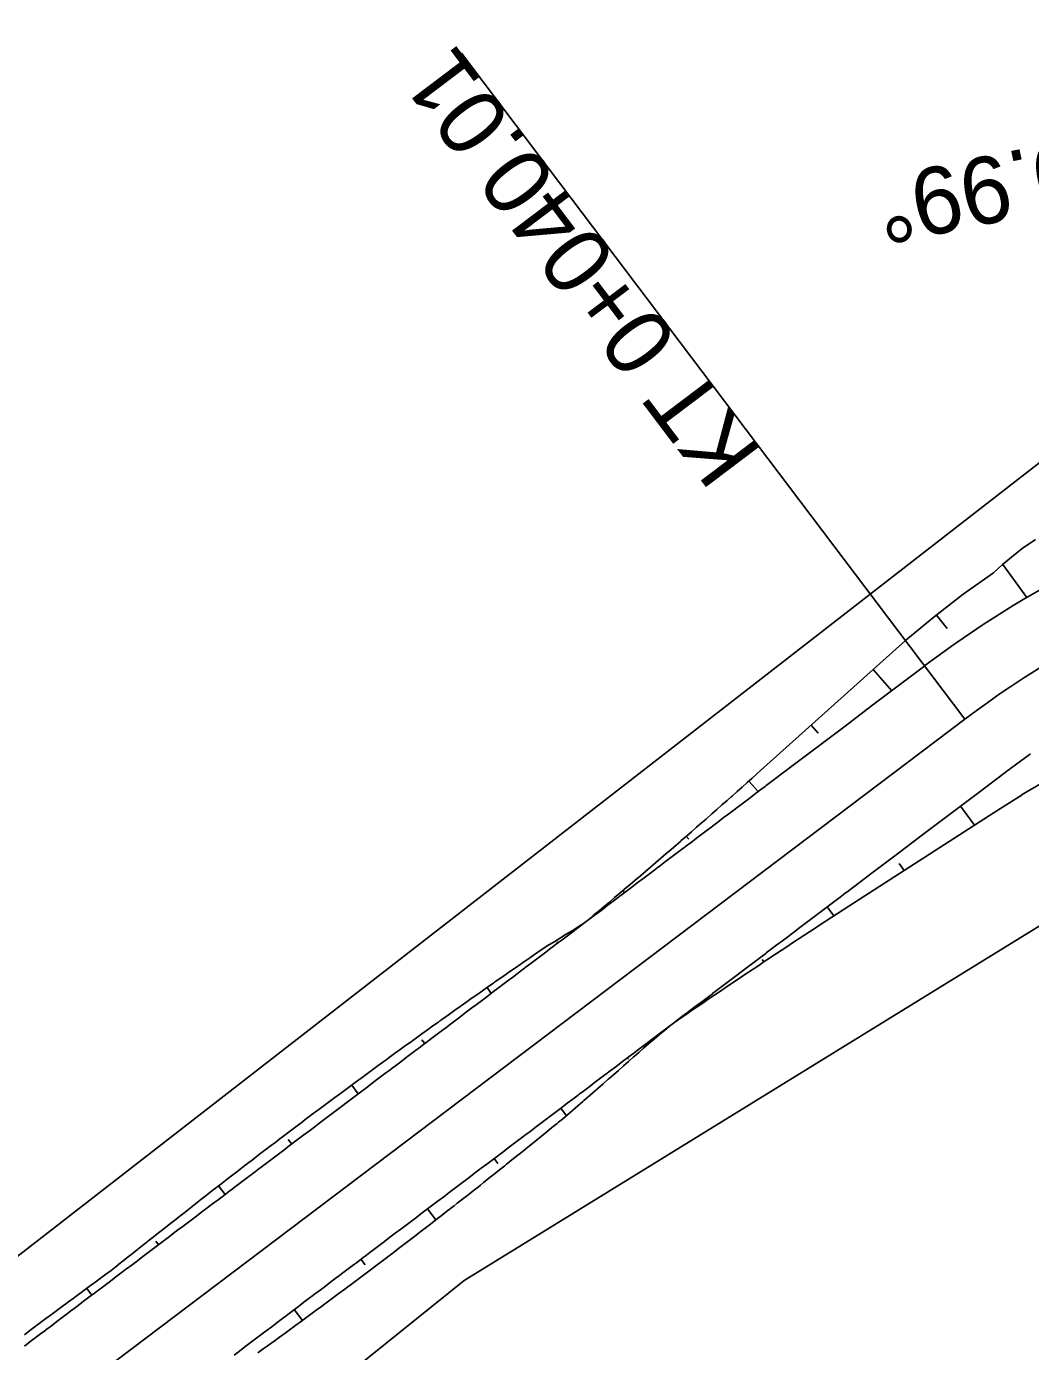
# Model space of a CAD drawing. Extents: x -583470 to -583050, y -1165714 to -1165417.
# Drawn here: x -583260.41 to -583230.35, y -1165547.32 to -1165507.64 of the extents above; entities that cross this region are included whole.
import ezdxf

# ---------------------------------------------------------------- set-up
doc = ezdxf.new("R2010")
doc.units = 0
for name, color, linetype in [('Hranice parcel', 7, 'Continuous'), ('Parcelní čísla', 7, 'Continuous'), ('Rám', 7, 'Continuous'), ('Sítě', 7, 'Continuous'), ('Šrafy', 7, 'Continuous')]:
    doc.layers.add(name, color=color, linetype=linetype)

msp = doc.modelspace()

# ---------------------------------------------------------------- linework, layer by layer
at = {"layer": 'Hranice parcel'}
msp.add_lwpolyline([(-583232.311, -1165528.379), (-583247.383, -1165508.433)], dxfattribs=at)
at = {"layer": 'Parcelní čísla'}
msp.add_line((-583232.311, -1165528.379), (-583286.571, -1165569.38), dxfattribs=at)
msp.add_arc((-583214.224, -1165552.314), 30, 76.0815, 127.0765, dxfattribs=at)
at = {"layer": 'Rám'}
for points in [[(-583348.01, -1165573.19), (-583304.26, -1165570.92), (-583288.23, -1165565.85), (-583222.91, -1165515.13), (-583194.86, -1165515.1)], [(-583202.69, -1165538.68), (-583225.12, -1165531.51), (-583247.31, -1165545.19), (-583283.21, -1165574.06), (-583292.71, -1165580.22), (-583304.73, -1165581.14), (-583316.86, -1165578.96), (-583335.26, -1165581.29), (-583341.42, -1165583.09), (-583347.21, -1165586.62), (-583351.13, -1165592.35), (-583353.34, -1165595.85), (-583354.98, -1165601.64), (-583352.56, -1165623.43)]]:
    msp.add_lwpolyline(points, dxfattribs=at)
at = {"layer": 'Sítě'}
for points in [[(-583260.474, -1165546.812), (-583260.313, -1165546.691), (-583260.151, -1165546.57), (-583259.999, -1165546.456), (-583259.989, -1165546.449), (-583259.828, -1165546.328), (-583259.666, -1165546.208), (-583259.504, -1165546.088), (-583259.342, -1165545.968), (-583259.196, -1165545.86), (-583259.18, -1165545.848), (-583259.017, -1165545.728), (-583258.855, -1165545.608), (-583258.692, -1165545.489), (-583258.53, -1165545.369), (-583258.391, -1165545.267), (-583258.367, -1165545.25), (-583258.204, -1165545.131), (-583258.041, -1165545.012), (-583257.878, -1165544.893), (-583257.721, -1165544.767), (-583257.593, -1165544.664), (-583257.563, -1165544.64), (-583257.406, -1165544.514), (-583257.248, -1165544.388), (-583257.09, -1165544.263), (-583256.932, -1165544.137), (-583256.81, -1165544.041), (-583256.773, -1165544.012), (-583256.615, -1165543.888), (-583256.456, -1165543.764), (-583256.297, -1165543.639), (-583256.137, -1165543.515), (-583256.023, -1165543.425), (-583255.979, -1165543.39), (-583255.821, -1165543.265), (-583255.662, -1165543.141), (-583255.503, -1165543.016), (-583255.345, -1165542.891), (-583255.237, -1165542.807), (-583255.186, -1165542.767), (-583255.027, -1165542.643), (-583254.868, -1165542.519), (-583254.709, -1165542.395), (-583254.549, -1165542.271), (-583254.448, -1165542.192), (-583254.39, -1165542.147), (-583254.23, -1165542.024), (-583254.07, -1165541.901), (-583253.911, -1165541.778), (-583253.751, -1165541.655), (-583253.656, -1165541.582), (-583253.591, -1165541.532), (-583253.43, -1165541.409), (-583253.27, -1165541.287), (-583253.11, -1165541.164), (-583252.949, -1165541.042), (-583252.861, -1165540.975), (-583252.788, -1165540.92), (-583252.628, -1165540.798), (-583252.467, -1165540.676), (-583252.306, -1165540.555), (-583252.145, -1165540.434), (-583252.063, -1165540.372), (-583251.983, -1165540.312), (-583251.822, -1165540.191), (-583251.661, -1165540.07), (-583251.499, -1165539.95), (-583251.337, -1165539.829), (-583251.262, -1165539.773), (-583251.175, -1165539.708), (-583251.013, -1165539.588), (-583250.851, -1165539.468), (-583250.689, -1165539.348), (-583250.527, -1165539.228), (-583250.458, -1165539.178), (-583250.364, -1165539.109), (-583250.202, -1165538.989), (-583250.039, -1165538.87), (-583249.876, -1165538.75), (-583249.713, -1165538.631), (-583249.652, -1165538.587), (-583249.55, -1165538.513), (-583249.387, -1165538.394), (-583249.224, -1165538.275), (-583249.061, -1165538.157), (-583248.897, -1165538.039), (-583248.842, -1165537.999), (-583248.733, -1165537.921), (-583248.57, -1165537.803), (-583248.406, -1165537.685), (-583248.242, -1165537.567), (-583248.078, -1165537.45), (-583248.03, -1165537.416), (-583247.913, -1165537.332), (-583247.749, -1165537.215), (-583247.585, -1165537.098), (-583247.42, -1165536.981), (-583247.255, -1165536.865), (-583247.215, -1165536.836), (-583247.091, -1165536.748), (-583246.926, -1165536.632), (-583246.761, -1165536.516), (-583246.595, -1165536.4), (-583246.43, -1165536.284), (-583246.396, -1165536.26), (-583246.265, -1165536.168), (-583246.099, -1165536.052), (-583245.933, -1165535.937), (-583245.768, -1165535.822), (-583245.602, -1165535.707), (-583245.575, -1165535.688), (-583245.436, -1165535.592), (-583245.27, -1165535.477), (-583245.103, -1165535.362), (-583244.937, -1165535.248), (-583244.766, -1165535.139), (-583244.746, -1165535.127), (-583244.594, -1165535.033), (-583244.421, -1165534.927), (-583244.248, -1165534.821), (-583244.076, -1165534.715), (-583243.903, -1165534.609), (-583243.89, -1165534.601), (-583243.732, -1165534.5), (-583243.575, -1165534.374), (-583243.42, -1165534.244), (-583243.265, -1165534.115), (-583243.105, -1165533.981), (-583242.955, -1165533.855), (-583242.801, -1165533.725), (-583242.646, -1165533.594), (-583242.492, -1165533.464), (-583242.338, -1165533.333), (-583242.184, -1165533.202), (-583242.03, -1165533.071), (-583241.877, -1165532.94), (-583241.723, -1165532.809), (-583241.578, -1165532.684), (-583241.57, -1165532.677), (-583241.416, -1165532.545), (-583241.263, -1165532.413), (-583241.11, -1165532.281), (-583240.957, -1165532.149), (-583240.819, -1165532.029), (-583240.804, -1165532.016), (-583240.652, -1165531.884), (-583240.499, -1165531.751), (-583240.347, -1165531.618), (-583240.195, -1165531.485), (-583240.064, -1165531.37), (-583240.043, -1165531.351), (-583239.891, -1165531.218), (-583239.739, -1165531.084), (-583239.587, -1165530.95), (-583239.435, -1165530.816), (-583239.312, -1165530.707), (-583239.284, -1165530.682), (-583239.133, -1165530.548), (-583238.982, -1165530.413), (-583238.831, -1165530.278), (-583238.68, -1165530.143), (-583238.563, -1165530.039), (-583238.529, -1165530.008), (-583234.089, -1165526.025), (-583234.08, -1165526.018), (-583233.233, -1165525.314), (-583233.145, -1165525.243), (-583232.359, -1165524.64), (-583232.168, -1165524.5), (-583231.46, -1165523.996), (-583231.185, -1165523.751), (-583230.602, -1165523.268), (-583230.194, -1165522.995)], [(-583229.941, -1165524.439), (-583230.563, -1165524.799), (-583230.862, -1165524.979), (-583231.571, -1165525.424), (-583231.763, -1165525.548), (-583232.556, -1165526.085), (-583232.646, -1165526.148), (-583233.507, -1165526.776), (-583233.516, -1165526.783), (-583234.306, -1165527.38), (-583235.104, -1165527.982), (-583235.901, -1165528.585), (-583236.699, -1165529.188), (-583237.497, -1165529.791), (-583238.258, -1165530.366), (-583238.295, -1165530.394), (-583238.419, -1165530.488), (-583238.58, -1165530.61), (-583238.741, -1165530.731), (-583238.902, -1165530.853), (-583239.063, -1165530.974), (-583239.093, -1165530.997), (-583239.224, -1165531.096), (-583239.385, -1165531.218), (-583239.546, -1165531.339), (-583239.707, -1165531.461), (-583239.868, -1165531.583), (-583239.891, -1165531.6), (-583240.029, -1165531.704), (-583240.19, -1165531.826), (-583240.351, -1165531.947), (-583240.512, -1165532.069), (-583240.673, -1165532.191), (-583240.688, -1165532.203), (-583240.834, -1165532.312), (-583240.995, -1165532.434), (-583241.156, -1165532.556), (-583241.316, -1165532.677), (-583241.477, -1165532.799), (-583241.486, -1165532.806), (-583241.638, -1165532.92), (-583241.799, -1165533.042), (-583241.96, -1165533.164), (-583242.121, -1165533.285), (-583242.282, -1165533.407), (-583242.284, -1165533.408), (-583242.443, -1165533.529), (-583242.604, -1165533.65), (-583242.765, -1165533.772), (-583242.926, -1165533.894), (-583243.082, -1165534.011), (-583243.087, -1165534.015), (-583243.248, -1165534.137), (-583243.409, -1165534.258), (-583243.57, -1165534.38), (-583243.731, -1165534.502), (-583243.88, -1165534.614), (-583243.892, -1165534.623), (-583244.053, -1165534.745), (-583244.214, -1165534.867), (-583244.375, -1165534.988), (-583244.536, -1165535.11), (-583244.678, -1165535.217), (-583244.697, -1165535.231), (-583244.858, -1165535.353), (-583245.019, -1165535.475), (-583245.179, -1165535.596), (-583245.34, -1165535.718), (-583245.475, -1165535.82), (-583245.501, -1165535.84), (-583245.662, -1165535.961), (-583245.823, -1165536.083), (-583245.984, -1165536.204), (-583246.145, -1165536.326), (-583246.273, -1165536.423), (-583246.306, -1165536.448), (-583246.467, -1165536.569), (-583246.628, -1165536.691), (-583246.789, -1165536.813), (-583246.95, -1165536.934), (-583247.071, -1165537.026), (-583247.111, -1165537.056), (-583247.272, -1165537.177), (-583247.433, -1165537.299), (-583247.594, -1165537.421), (-583247.755, -1165537.542), (-583247.869, -1165537.629), (-583247.916, -1165537.664), (-583248.077, -1165537.786), (-583248.238, -1165537.907), (-583248.399, -1165538.029), (-583248.56, -1165538.15), (-583248.667, -1165538.231), (-583248.721, -1165538.272), (-583248.882, -1165538.394), (-583249.042, -1165538.515), (-583249.203, -1165538.637), (-583249.364, -1165538.759), (-583249.465, -1165538.834), (-583249.525, -1165538.88), (-583249.686, -1165539.002), (-583249.847, -1165539.124), (-583250.008, -1165539.245), (-583250.169, -1165539.367), (-583250.262, -1165539.437), (-583250.33, -1165539.488), (-583250.491, -1165539.61), (-583250.652, -1165539.732), (-583250.813, -1165539.853), (-583250.974, -1165539.975), (-583251.06, -1165540.04), (-583251.135, -1165540.097), (-583251.296, -1165540.218), (-583251.457, -1165540.34), (-583251.618, -1165540.461), (-583251.779, -1165540.583), (-583251.858, -1165540.643), (-583251.94, -1165540.705), (-583252.101, -1165540.826), (-583252.262, -1165540.948), (-583252.423, -1165541.07), (-583252.584, -1165541.191), (-583252.656, -1165541.246), (-583252.745, -1165541.313), (-583252.905, -1165541.434), (-583253.066, -1165541.556), (-583253.227, -1165541.678), (-583253.388, -1165541.799), (-583253.454, -1165541.849), (-583253.549, -1165541.921), (-583253.71, -1165542.043), (-583253.871, -1165542.164), (-583254.032, -1165542.286), (-583254.193, -1165542.407), (-583254.252, -1165542.452), (-583254.354, -1165542.529), (-583254.515, -1165542.651), (-583254.676, -1165542.772), (-583254.837, -1165542.894), (-583254.998, -1165543.016), (-583255.049, -1165543.055), (-583255.159, -1165543.137), (-583255.32, -1165543.259), (-583255.481, -1165543.38), (-583255.642, -1165543.502), (-583255.803, -1165543.624), (-583255.847, -1165543.657), (-583255.964, -1165543.745), (-583256.125, -1165543.867), (-583256.286, -1165543.989), (-583256.447, -1165544.11), (-583256.608, -1165544.232), (-583256.645, -1165544.26), (-583256.768, -1165544.354), (-583256.929, -1165544.475), (-583257.09, -1165544.597), (-583257.251, -1165544.718), (-583257.412, -1165544.84), (-583257.443, -1165544.863), (-583257.573, -1165544.962), (-583257.734, -1165545.083), (-583257.895, -1165545.205), (-583258.056, -1165545.327), (-583258.217, -1165545.448), (-583258.241, -1165545.466), (-583258.378, -1165545.57), (-583258.539, -1165545.691), (-583258.7, -1165545.813), (-583258.861, -1165545.935), (-583259.022, -1165546.056), (-583259.039, -1165546.069), (-583259.183, -1165546.178), (-583259.344, -1165546.3), (-583259.505, -1165546.421), (-583259.666, -1165546.543), (-583259.827, -1165546.664), (-583259.836, -1165546.672), (-583259.988, -1165546.786), (-583260.149, -1165546.908), (-583260.31, -1165547.029), (-583260.471, -1165547.151)], [(-583230.343, -1165529.419), (-583231.097, -1165529.968), (-583231.105, -1165529.974), (-583231.894, -1165530.571), (-583232.692, -1165531.174), (-583233.49, -1165531.777), (-583234.288, -1165532.38), (-583235.086, -1165532.982), (-583235.847, -1165533.558), (-583235.883, -1165533.585), (-583236.008, -1165533.679), (-583236.169, -1165533.801), (-583236.33, -1165533.923), (-583236.491, -1165534.044), (-583236.652, -1165534.166), (-583236.681, -1165534.188), (-583236.813, -1165534.287), (-583236.973, -1165534.409), (-583237.134, -1165534.531), (-583237.295, -1165534.652), (-583237.456, -1165534.774), (-583237.479, -1165534.791), (-583237.617, -1165534.896), (-583237.778, -1165535.017), (-583237.939, -1165535.139), (-583238.1, -1165535.26), (-583238.261, -1165535.382), (-583238.277, -1165535.394), (-583238.422, -1165535.504), (-583238.583, -1165535.625), (-583238.744, -1165535.747), (-583238.905, -1165535.869), (-583239.066, -1165535.99), (-583239.075, -1165535.997), (-583239.227, -1165536.112), (-583239.388, -1165536.233), (-583239.549, -1165536.355), (-583239.71, -1165536.477), (-583239.871, -1165536.598), (-583239.873, -1165536.6), (-583240.032, -1165536.72), (-583240.193, -1165536.842), (-583240.354, -1165536.963), (-583240.515, -1165537.085), (-583240.67, -1165537.203), (-583240.676, -1165537.206), (-583240.836, -1165537.328), (-583240.997, -1165537.45), (-583241.158, -1165537.571), (-583241.319, -1165537.693), (-583241.468, -1165537.806), (-583241.48, -1165537.815), (-583241.641, -1165537.936), (-583241.802, -1165538.058), (-583241.963, -1165538.179), (-583242.124, -1165538.301), (-583242.266, -1165538.408), (-583242.285, -1165538.423), (-583242.446, -1165538.544), (-583242.607, -1165538.666), (-583242.768, -1165538.788), (-583242.929, -1165538.909), (-583243.064, -1165539.011), (-583243.09, -1165539.031), (-583243.251, -1165539.153), (-583243.412, -1165539.274), (-583243.573, -1165539.396), (-583243.734, -1165539.517), (-583243.862, -1165539.614), (-583243.895, -1165539.639), (-583244.056, -1165539.761), (-583244.217, -1165539.882), (-583244.378, -1165540.004), (-583244.539, -1165540.126), (-583244.66, -1165540.217), (-583244.699, -1165540.247), (-583244.86, -1165540.369), (-583245.021, -1165540.49), (-583245.182, -1165540.612), (-583245.343, -1165540.734), (-583245.457, -1165540.82), (-583245.504, -1165540.855), (-583245.665, -1165540.977), (-583245.826, -1165541.099), (-583245.987, -1165541.22), (-583246.148, -1165541.342), (-583246.255, -1165541.423), (-583246.309, -1165541.463), (-583246.47, -1165541.585), (-583246.631, -1165541.707), (-583246.792, -1165541.828), (-583246.953, -1165541.95), (-583247.053, -1165542.026), (-583247.114, -1165542.072), (-583247.275, -1165542.193), (-583247.436, -1165542.315), (-583247.597, -1165542.436), (-583247.758, -1165542.558), (-583247.851, -1165542.629), (-583247.919, -1165542.68), (-583248.08, -1165542.801), (-583248.241, -1165542.923), (-583248.402, -1165543.045), (-583248.562, -1165543.166), (-583248.649, -1165543.231), (-583248.723, -1165543.288), (-583248.884, -1165543.409), (-583249.045, -1165543.531), (-583249.206, -1165543.653), (-583249.367, -1165543.774), (-583249.447, -1165543.834), (-583249.528, -1165543.896), (-583249.689, -1165544.018), (-583249.85, -1165544.139), (-583250.011, -1165544.261), (-583250.172, -1165544.383), (-583250.244, -1165544.437), (-583250.333, -1165544.504), (-583250.494, -1165544.626), (-583250.655, -1165544.747), (-583250.816, -1165544.869), (-583250.977, -1165544.991), (-583251.042, -1165545.04), (-583251.138, -1165545.112), (-583251.299, -1165545.234), (-583251.46, -1165545.356), (-583251.621, -1165545.477), (-583251.782, -1165545.599), (-583251.84, -1165545.643), (-583251.943, -1165545.72), (-583252.104, -1165545.842), (-583252.265, -1165545.964), (-583252.425, -1165546.085), (-583252.586, -1165546.207), (-583252.638, -1165546.246), (-583252.747, -1165546.329), (-583252.908, -1165546.45), (-583253.069, -1165546.572), (-583253.23, -1165546.693), (-583253.391, -1165546.815), (-583253.436, -1165546.849), (-583253.552, -1165546.937), (-583253.713, -1165547.058), (-583253.874, -1165547.18), (-583254.035, -1165547.302), (-583254.196, -1165547.423)], [(-583229.812, -1165530.173), (-583230.593, -1165530.636), (-583230.601, -1165530.641), (-583231.436, -1165531.177), (-583235.613, -1165533.867), (-583235.651, -1165533.892), (-583235.783, -1165533.977), (-583235.953, -1165534.087), (-583236.122, -1165534.197), (-583236.292, -1165534.307), (-583236.462, -1165534.417), (-583236.493, -1165534.438), (-583236.631, -1165534.528), (-583236.8, -1165534.638), (-583236.97, -1165534.749), (-583237.139, -1165534.86), (-583237.308, -1165534.971), (-583237.332, -1165534.986), (-583237.477, -1165535.082), (-583237.645, -1165535.193), (-583237.814, -1165535.305), (-583237.982, -1165535.416), (-583238.151, -1165535.528), (-583238.167, -1165535.539), (-583238.319, -1165535.64), (-583238.487, -1165535.752), (-583238.655, -1165535.864), (-583238.823, -1165535.977), (-583238.991, -1165536.089), (-583239, -1165536.095), (-583239.159, -1165536.202), (-583239.326, -1165536.315), (-583239.494, -1165536.428), (-583239.661, -1165536.541), (-583239.83, -1165536.656), (-583239.996, -1165536.768), (-583240.163, -1165536.881), (-583240.329, -1165536.995), (-583240.496, -1165537.109), (-583240.663, -1165537.223), (-583240.829, -1165537.338), (-583240.996, -1165537.452), (-583241.154, -1165537.577), (-583241.309, -1165537.706), (-583241.453, -1165537.826), (-583241.465, -1165537.835), (-583241.62, -1165537.964), (-583241.776, -1165538.093), (-583241.928, -1165538.226), (-583242.079, -1165538.36), (-583242.213, -1165538.479), (-583242.231, -1165538.495), (-583242.382, -1165538.629), (-583242.534, -1165538.763), (-583242.686, -1165538.897), (-583242.837, -1165539.03), (-583242.965, -1165539.142), (-583242.989, -1165539.164), (-583243.141, -1165539.297), (-583243.294, -1165539.43), (-583243.446, -1165539.563), (-583243.599, -1165539.696), (-583243.72, -1165539.802), (-583243.751, -1165539.829), (-583243.904, -1165539.961), (-583244.057, -1165540.094), (-583244.21, -1165540.226), (-583244.364, -1165540.356), (-583244.482, -1165540.452), (-583244.521, -1165540.484), (-583244.677, -1165540.611), (-583244.834, -1165540.739), (-583244.99, -1165540.866), (-583245.147, -1165540.993), (-583245.259, -1165541.083), (-583245.304, -1165541.12), (-583245.461, -1165541.247), (-583245.619, -1165541.373), (-583245.776, -1165541.5), (-583245.933, -1165541.626), (-583246.038, -1165541.71), (-583246.091, -1165541.752), (-583246.249, -1165541.878), (-583246.407, -1165542.004), (-583246.565, -1165542.129), (-583246.723, -1165542.254), (-583246.821, -1165542.332), (-583246.881, -1165542.38), (-583247.04, -1165542.504), (-583247.198, -1165542.629), (-583247.357, -1165542.754), (-583247.516, -1165542.878), (-583247.608, -1165542.95), (-583247.675, -1165543.003), (-583247.834, -1165543.127), (-583247.993, -1165543.251), (-583248.152, -1165543.374), (-583248.312, -1165543.498), (-583248.397, -1165543.564), (-583248.472, -1165543.621), (-583248.631, -1165543.744), (-583248.791, -1165543.867), (-583248.951, -1165543.99), (-583249.111, -1165544.113), (-583249.19, -1165544.173), (-583249.272, -1165544.235), (-583249.432, -1165544.358), (-583249.593, -1165544.48), (-583249.753, -1165544.602), (-583249.914, -1165544.724), (-583249.987, -1165544.778), (-583250.075, -1165544.845), (-583250.236, -1165544.967), (-583250.398, -1165545.088), (-583250.559, -1165545.209), (-583250.721, -1165545.33), (-583250.786, -1165545.379), (-583250.882, -1165545.45), (-583251.044, -1165545.571), (-583251.206, -1165545.691), (-583251.368, -1165545.812), (-583251.53, -1165545.932), (-583251.589, -1165545.975), (-583251.693, -1165546.051), (-583251.855, -1165546.171), (-583252.018, -1165546.29), (-583252.18, -1165546.41), (-583252.343, -1165546.529), (-583252.395, -1165546.567), (-583252.506, -1165546.648), (-583252.669, -1165546.767), (-583252.833, -1165546.885), (-583252.996, -1165547.003), (-583253.16, -1165547.122), (-583253.205, -1165547.154), (-583253.323, -1165547.24), (-583253.487, -1165547.358)]]:
    msp.add_lwpolyline(points, dxfattribs=at)
at = {"layer": 'Šrafy'}
for p, q in [((-583231.18, -1165523.746), (-583230.458, -1165524.739)), ((-583232.842, -1165525.66), (-583233.166, -1165525.261)), ((-583235.058, -1165526.894), (-583234.501, -1165527.527)), ((-583236.708, -1165528.799), (-583236.919, -1165528.564)), ((-583238.78, -1165530.233), (-583238.5, -1165530.549)), ((-583232.022, -1165531.555), (-583232.448, -1165530.989)), ((-583240.579, -1165531.974), (-583240.655, -1165531.887)), ((-583234.285, -1165532.704), (-583234.128, -1165532.912)), ((-583242.552, -1165533.515), (-583242.504, -1165533.575)), ((-583236.235, -1165534.27), (-583236.437, -1165534.004)), ((-583244.524, -1165535.044), (-583244.498, -1165535.081)), ((-583238.38, -1165535.579), (-583238.329, -1165535.646)), ((-583246.616, -1165536.414), (-583246.494, -1165536.59)), ((-583240.404, -1165537.046), (-583240.426, -1165537.018)), ((-583248.57, -1165537.979), (-583248.486, -1165538.095)), ((-583242.389, -1165538.566), (-583242.421, -1165538.525)), ((-583250.673, -1165539.336), (-583250.478, -1165539.6)), ((-583244.246, -1165540.256), (-583244.415, -1165540.032)), ((-583252.572, -1165540.97), (-583252.47, -1165541.105)), ((-583246.3, -1165541.685), (-583246.41, -1165541.54)), ((-583254.659, -1165542.356), (-583254.461, -1165542.61)), ((-583248.155, -1165543.376), (-583248.404, -1165543.047)), ((-583256.541, -1165544.007), (-583256.456, -1165544.117)), ((-583250.27, -1165544.724), (-583250.399, -1165544.554)), ((-583258.605, -1165545.425), (-583258.453, -1165545.626)), ((-583252.148, -1165546.386), (-583252.393, -1165546.061))]:
    msp.add_line(p, q, dxfattribs=at)

# ---------------------------------------------------------------- texts
at = {"layer": 'Hranice parcel'}
for s, rotation, p in [('R=30m alfa=50.99%%d', 191.579, (-583212.521, -1165507.593)), ('KT 0+040.01', 127.0765, (-583238.339, -1165520.4))]:
    msp.add_text(s, height=2, rotation=rotation, dxfattribs=at).set_placement(p)

doc.saveas('drawing.dxf')
